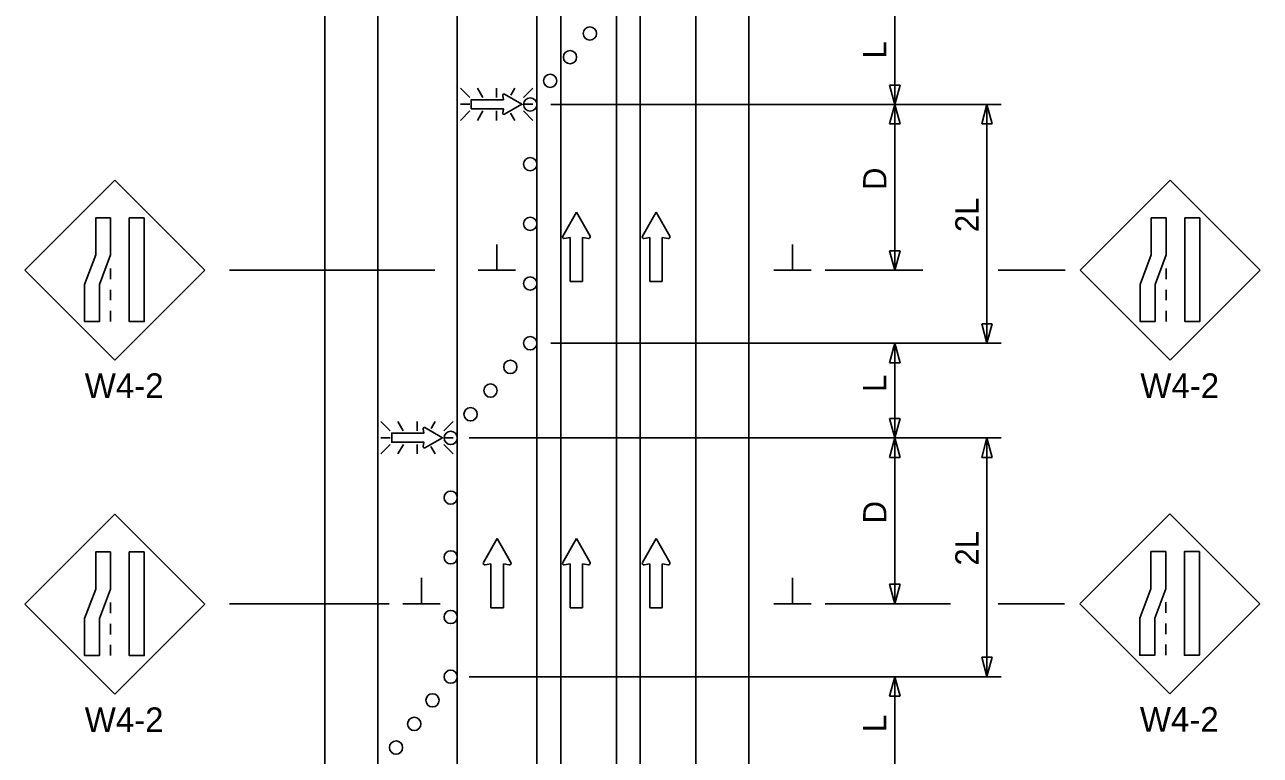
# Model space of a CAD drawing. Extents: x 16725 to 18479, y 5932 to 7023.
# Drawn here: x 16768.2 to 17141, y 6511.8 to 6732.2 of the extents above; entities that cross this region are included whole.
import ezdxf

# ---------------------------------------------------------------- set-up
doc = ezdxf.new("R2010")
doc.units = 0
for name, color, linetype in [('ALI_LEGAL_EX', 7, 'Continuous'), ('MT_SCRATCH_LEVEL_E', 7, 'Continuous'), ('PAVT_EDGE_EX', 7, 'Continuous'), ('TRAFFIC_SIGNS_PR', 7, 'Continuous'), ('TYPICAL_TEXT_DIMEN_PR', 7, 'Continuous')]:
    doc.layers.add(name, color=color, linetype=linetype)

msp = doc.modelspace()

# ---------------------------------------------------------------- linework, layer by layer
at = {"layer": 'ALI_LEGAL_EX'}
for p, q in [((16898.69, 7022.86), (16898.69, 6323.13)), ((16922.69, 7022.86), (16922.69, 6323.13)), ((16946.69, 7022.86), (16946.69, 6323.13)), ((16929.88, 7005.57), (16929.88, 6176.39)), ((16953.88, 7005.57), (16953.88, 6176.39)), ((16953.88, 7005.57), (16953.88, 6176.39))]:
    msp.add_line(p, q, dxfattribs=at)
for points in [[(16898.69, 6682.86), (16898.69, 6657.86)], [(16922.69, 6682.86), (16922.69, 6657.86)], [(16946.69, 6682.86), (16946.69, 6657.86)], [(16898.69, 6582.86), (16898.69, 6557.86)], [(16922.69, 6582.86), (16922.69, 6557.86)], [(16946.69, 6582.86), (16946.69, 6557.86)]]:
    msp.add_lwpolyline(points, dxfattribs=at)
at = {"layer": 'MT_SCRATCH_LEVEL_E'}
for p, q in [((16934.6, 6675.63), (16930.49, 6668.39)), ((16938.74, 6668.39), (16934.6, 6675.63)), ((16958.65, 6675.63), (16954.54, 6668.39)), ((16962.8, 6668.39), (16958.65, 6675.63)), ((16930.97, 6667.71), (16932.74, 6668.02)), ((16932.74, 6668.02), (16932.74, 6654.77)), ((16936.49, 6654.77), (16936.49, 6668.02)), ((16936.49, 6668.02), (16938.26, 6667.71)), ((16955.02, 6667.71), (16956.8, 6668.02)), ((16956.8, 6668.02), (16956.8, 6654.77)), ((16960.54, 6654.77), (16960.54, 6668.02)), ((16960.54, 6668.02), (16962.32, 6667.71)), ((16932.74, 6654.77), (16936.49, 6654.77)), ((16956.8, 6654.77), (16960.54, 6654.77)), ((16910.69, 6577.17), (16906.58, 6569.93)), ((16914.84, 6569.93), (16910.69, 6577.17)), ((16934.6, 6577.17), (16930.49, 6569.93)), ((16938.74, 6569.93), (16934.6, 6577.17)), ((16958.65, 6577.17), (16954.54, 6569.93)), ((16962.8, 6569.93), (16958.65, 6577.17)), ((16907.06, 6569.24), (16908.84, 6569.56)), ((16908.84, 6569.56), (16908.84, 6556.3)), ((16912.58, 6556.3), (16912.58, 6569.56)), ((16912.58, 6569.56), (16914.36, 6569.24)), ((16930.97, 6569.24), (16932.74, 6569.56)), ((16932.74, 6569.56), (16932.74, 6556.3)), ((16936.49, 6556.3), (16936.49, 6569.56)), ((16936.49, 6569.56), (16938.26, 6569.24)), ((16955.02, 6569.24), (16956.8, 6569.56)), ((16956.8, 6569.56), (16956.8, 6556.3)), ((16960.54, 6556.3), (16960.54, 6569.56)), ((16960.54, 6569.56), (16962.32, 6569.24)), ((16908.84, 6556.3), (16912.58, 6556.3)), ((16932.74, 6556.3), (16936.49, 6556.3)), ((16956.8, 6556.3), (16960.54, 6556.3))]:
    msp.add_line(p, q, dxfattribs=at)
for centre, start, end in [((16930.89, 6668.17), 150.4248, 279.9638), ((16938.33, 6668.17), 260.0362, 29.7731), ((16954.95, 6668.17), 150.4248, 279.9638), ((16962.39, 6668.17), 260.0362, 29.7731), ((16906.99, 6569.7), 150.4248, 279.9638), ((16914.43, 6569.7), 260.0362, 29.7731), ((16930.89, 6569.7), 150.4248, 279.9638), ((16938.33, 6569.7), 260.0362, 29.7731), ((16954.95, 6569.7), 150.4248, 279.9638), ((16962.39, 6569.7), 260.0362, 29.7731)]:
    msp.add_arc(centre, 0.463, start, end, dxfattribs=at)
at = {"layer": 'PAVT_EDGE_EX'}
for p, q in [((16858.69, 6927.61), (16858.69, 6189.52)), ((16874.69, 6927.61), (16874.69, 6189.52)), ((16970.69, 6927.61), (16970.69, 6189.52)), ((16986.69, 6927.61), (16986.69, 6189.52))]:
    msp.add_line(p, q, dxfattribs=at)
at = {"layer": 'TRAFFIC_SIGNS_PR'}
for p, q in [((16902.47, 6710.21), (16899.65, 6713.03)), ((16904.77, 6713.03), (16906.39, 6710.21)), ((16910.55, 6710.21), (16910.55, 6713.03)), ((16916.02, 6713.03), (16914.82, 6710.94)), ((16921.46, 6713.03), (16918.64, 6710.21)), ((16902.47, 6708.18), (16899.65, 6708.18)), ((16918.64, 6708.18), (16921.46, 6708.18)), ((16902.47, 6706.15), (16899.65, 6703.32)), ((16906.42, 6706.15), (16904.79, 6703.33)), ((16910.55, 6706.15), (16910.55, 6703.33)), ((16914.74, 6705.51), (16916, 6703.33)), ((16921.46, 6703.33), (16918.64, 6706.15)), ((16795.32, 6685.32), (16768.17, 6658.17)), ((16822.47, 6658.17), (16795.32, 6685.32)), ((17113.8, 6685.32), (17086.65, 6658.17)), ((17140.96, 6658.17), (17113.8, 6685.32)), ((16768.17, 6658.17), (16795.32, 6631.02)), ((16794.07, 6658.66), (16794.07, 6655.46)), ((16795.32, 6631.02), (16822.47, 6658.17)), ((17086.65, 6658.17), (17113.8, 6631.02)), ((17112.56, 6658.66), (17112.56, 6655.46)), ((17113.8, 6631.02), (17140.96, 6658.17)), ((16794.07, 6652.26), (16794.07, 6649.06)), ((17112.56, 6652.26), (17112.56, 6649.06)), ((16794.07, 6645.86), (16794.07, 6642.66)), ((17112.56, 6645.86), (17112.56, 6642.66)), ((16878.47, 6609.65), (16875.65, 6612.47)), ((16880.77, 6612.47), (16882.39, 6609.65)), ((16886.55, 6609.65), (16886.55, 6612.47)), ((16892.02, 6612.47), (16890.82, 6610.37)), ((16897.46, 6612.47), (16894.64, 6609.65)), ((16878.47, 6607.61), (16875.65, 6607.61)), ((16894.64, 6607.61), (16897.46, 6607.61)), ((16878.47, 6605.58), (16875.65, 6602.76)), ((16882.42, 6605.58), (16880.79, 6602.76)), ((16886.55, 6605.58), (16886.55, 6602.76)), ((16890.74, 6604.95), (16892, 6602.76)), ((16897.46, 6602.77), (16894.64, 6605.58)), ((16795.32, 6584.57), (16768.17, 6557.42)), ((16822.47, 6557.42), (16795.32, 6584.57)), ((17113.68, 6584.66), (17086.53, 6557.51)), ((17140.83, 6557.51), (17113.68, 6584.66)), ((16768.17, 6557.42), (16795.32, 6530.27)), ((16794.07, 6557.91), (16794.07, 6554.71)), ((16795.32, 6530.27), (16822.47, 6557.42)), ((17086.53, 6557.51), (17113.68, 6530.36)), ((17112.43, 6558), (17112.43, 6554.8)), ((17113.68, 6530.36), (17140.83, 6557.51)), ((16794.07, 6551.51), (16794.07, 6548.31)), ((17112.43, 6551.6), (17112.43, 6548.4)), ((16794.07, 6545.11), (16794.07, 6541.91)), ((17112.43, 6545.2), (17112.43, 6542))]:
    msp.add_line(p, q, dxfattribs=at)
for points in [[(16912.38, 6710.86), (16912.61, 6709.56), (16902.89, 6709.56), (16902.89, 6706.82), (16912.61, 6706.82), (16912.38, 6705.52)], [(16912.88, 6705.16), (16918.19, 6708.18), (16912.88, 6711.22)], [(16888.38, 6610.3), (16888.61, 6609), (16878.89, 6609), (16878.89, 6606.26), (16888.61, 6606.26), (16888.38, 6604.95)], [(16888.88, 6604.6), (16894.19, 6607.61), (16888.88, 6610.66)]]:
    msp.add_lwpolyline(points, dxfattribs=at)
for points in [[(16794.07, 6673.91), (16794.07, 6662.73), (16790.73, 6653.84), (16790.73, 6642.66), (16786.24, 6642.66), (16786.24, 6653.84), (16789.58, 6662.73), (16789.58, 6673.91)], [(16804.21, 6673.91), (16804.21, 6642.66), (16799.72, 6642.66), (16799.72, 6673.91)], [(17112.56, 6673.91), (17112.56, 6662.73), (17109.21, 6653.84), (17109.21, 6642.66), (17104.72, 6642.66), (17104.72, 6653.84), (17108.06, 6662.73), (17108.06, 6673.91)], [(17122.69, 6673.91), (17122.69, 6642.66), (17118.2, 6642.66), (17118.2, 6673.91)], [(16794.07, 6573.16), (16794.07, 6561.98), (16790.73, 6553.09), (16790.73, 6541.91), (16786.24, 6541.91), (16786.24, 6553.09), (16789.58, 6561.98), (16789.58, 6573.16)], [(16804.21, 6573.16), (16804.21, 6541.91), (16799.72, 6541.91), (16799.72, 6573.16)], [(17112.43, 6573.25), (17112.43, 6562.07), (17109.09, 6553.18), (17109.09, 6542), (17104.59, 6542), (17104.59, 6553.18), (17107.94, 6562.07), (17107.94, 6573.25)], [(17122.57, 6573.25), (17122.57, 6542), (17118.08, 6542), (17118.08, 6573.25)]]:
    msp.add_lwpolyline(points, close=True, dxfattribs=at)
for centre in [(16938.69, 6729.53), (16932.69, 6722.39), (16926.69, 6715.25), (16920.69, 6708.11), (16920.69, 6690.11), (16920.69, 6672.11), (16920.69, 6654.11), (16920.69, 6636.11), (16914.69, 6628.97), (16908.69, 6621.83), (16902.69, 6614.69), (16896.69, 6607.55), (16896.69, 6589.54), (16896.69, 6571.54), (16896.69, 6553.54), (16896.69, 6535.54), (16891.2, 6528.41), (16885.7, 6521.29), (16880.2, 6514.16)]:
    msp.add_circle(centre, 2, dxfattribs=at)
for centre, start, end in [((16912.72, 6710.92), 61.4833, 189.9593), ((16912.72, 6705.46), 170.7308, 298.8916), ((16888.72, 6610.36), 61.4833, 189.9593), ((16888.72, 6604.9), 170.7308, 298.8916)]:
    msp.add_arc(centre, 0.341, start, end, dxfattribs=at)
at = {"layer": 'TYPICAL_TEXT_DIMEN_PR'}
for p, q in [((17030.69, 6708.11), (17030.69, 6738.67)), ((17030.69, 6708.11), (17029.12, 6713.97)), ((17029.12, 6713.97), (17030.69, 6713.97)), ((17030.69, 6713.97), (17032.26, 6713.97)), ((17032.26, 6713.97), (17030.69, 6708.11)), ((17062.74, 6708.11), (16926.92, 6708.11)), ((17029.12, 6702.24), (17030.69, 6708.11)), ((17030.69, 6708.11), (17030.69, 6658.11)), ((17030.69, 6708.11), (17032.26, 6702.24)), ((17056.93, 6702.24), (17058.5, 6708.11)), ((17058.5, 6708.11), (17060.07, 6702.24)), ((17058.5, 6708.11), (17058.5, 6636.11)), ((17030.69, 6702.24), (17029.12, 6702.24)), ((17032.26, 6702.24), (17030.69, 6702.24)), ((17058.5, 6702.24), (17056.93, 6702.24)), ((17060.07, 6702.24), (17058.5, 6702.24)), ((16910.64, 6658.11), (16910.64, 6665.89)), ((16999.82, 6658.11), (16999.82, 6665.89)), ((17030.69, 6658.11), (17029.12, 6663.97)), ((17029.12, 6663.97), (17030.69, 6663.97)), ((17030.69, 6663.97), (17032.26, 6663.97)), ((17032.26, 6663.97), (17030.69, 6658.11)), ((17058.5, 6662.98), (17058.5, 6659.21)), ((16829.94, 6658.11), (16891.95, 6658.11)), ((16916.26, 6658.11), (16905.01, 6658.11)), ((17005.44, 6658.11), (16994.19, 6658.11)), ((17039.11, 6658.11), (17009.69, 6658.11)), ((17082.1, 6658.11), (17061.87, 6658.11)), ((17058.5, 6636.11), (17056.93, 6641.97)), ((17056.93, 6641.97), (17058.5, 6641.97)), ((17058.5, 6641.97), (17060.07, 6641.97)), ((17060.07, 6641.97), (17058.5, 6636.11)), ((16926.92, 6636.11), (17062.74, 6636.11)), ((17029.12, 6630.24), (17030.69, 6636.11)), ((17030.69, 6607.55), (17030.69, 6636.11)), ((17030.69, 6636.11), (17032.26, 6630.24)), ((17030.69, 6630.24), (17029.12, 6630.24)), ((17032.26, 6630.24), (17030.69, 6630.24)), ((17030.69, 6607.55), (17029.12, 6613.41)), ((17029.12, 6613.41), (17030.69, 6613.41)), ((17030.69, 6613.41), (17032.26, 6613.41)), ((17032.26, 6613.41), (17030.69, 6607.55)), ((16902.24, 6607.55), (17062.74, 6607.55)), ((17029.12, 6601.68), (17030.69, 6607.55)), ((17030.69, 6607.55), (17030.69, 6557.55)), ((17030.69, 6607.55), (17032.26, 6601.68)), ((17056.93, 6601.68), (17058.5, 6607.55)), ((17058.5, 6607.55), (17060.07, 6601.68)), ((17058.5, 6607.55), (17058.5, 6535.55)), ((17030.69, 6601.68), (17029.12, 6601.68)), ((17032.26, 6601.68), (17030.69, 6601.68)), ((17058.5, 6601.68), (17056.93, 6601.68)), ((17060.07, 6601.68), (17058.5, 6601.68)), ((16887.91, 6557.55), (16887.91, 6565.33)), ((16999.82, 6557.55), (16999.82, 6565.33)), ((17030.69, 6557.55), (17029.12, 6563.41)), ((17029.12, 6563.41), (17030.69, 6563.41)), ((17030.69, 6563.41), (17032.26, 6563.41)), ((17032.26, 6563.41), (17030.69, 6557.55)), ((17058.5, 6562.41), (17058.5, 6558.65)), ((16829.94, 6557.55), (16878.12, 6557.55)), ((16893.53, 6557.55), (16882.28, 6557.55)), ((17005.44, 6557.55), (16994.19, 6557.55)), ((17047.53, 6557.55), (17009.69, 6557.55)), ((17081.86, 6557.55), (17061.87, 6557.55)), ((17058.5, 6535.55), (17056.93, 6541.41)), ((17056.93, 6541.41), (17058.5, 6541.41)), ((17058.5, 6541.41), (17060.07, 6541.41)), ((17060.07, 6541.41), (17058.5, 6535.55)), ((16902.24, 6535.54), (17062.74, 6535.54)), ((17029.12, 6529.68), (17030.69, 6535.54)), ((17030.69, 6504.98), (17030.69, 6535.54)), ((17030.69, 6535.54), (17032.26, 6529.68)), ((17030.69, 6529.68), (17029.12, 6529.68)), ((17032.26, 6529.68), (17030.69, 6529.68))]:
    msp.add_line(p, q, dxfattribs=at)

# ---------------------------------------------------------------- texts
at = {"layer": 'TRAFFIC_SIGNS_PR'}
for p in [(16786.28, 6619.58), (17104.76, 6619.58), (16786.28, 6518.83), (17104.64, 6518.92)]:
    msp.add_text('W4-2', height=7.44, dxfattribs=at).set_placement(p)
at = {"layer": 'TYPICAL_TEXT_DIMEN_PR'}
for s, p in [('L', (17028.14, 6721.96)), ('D', (17028.14, 6682.33)), ('2L', (17055.94, 6669.61)), ('L', (17028.14, 6621.4)), ('D', (17028.14, 6581.76)), ('2L', (17055.94, 6569.05)), ('L', (17028.14, 6518.84))]:
    msp.add_text(s, height=7, rotation=90, dxfattribs=at).set_placement(p)

doc.saveas('drawing.dxf')
